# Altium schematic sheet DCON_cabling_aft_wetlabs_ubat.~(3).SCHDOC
size B; Organization: Monterey Bay Aquarium Research Institute; Address1: 7700 Sandholdt Rd; Address2: Moss Landing, CA 95039-9644; CompanyName: MBARI; PageSetup: Record=PageOptions|CenterHorizontal=True|CenterVertical=True|PrintScale=0.70|XCorrection=1.00|YCorrection=1.00|PrintKind=0|BorderSize=5000000|LeftOffset=0|BottomOffset=0|Orientation=2|PaperLength=1000|PaperWidth=1000|Scale=100|PaperSource=7|PrintQuality=-4|MediaType=1|DitherType=10|PaperKind=Letter|PrintScaleMode=1
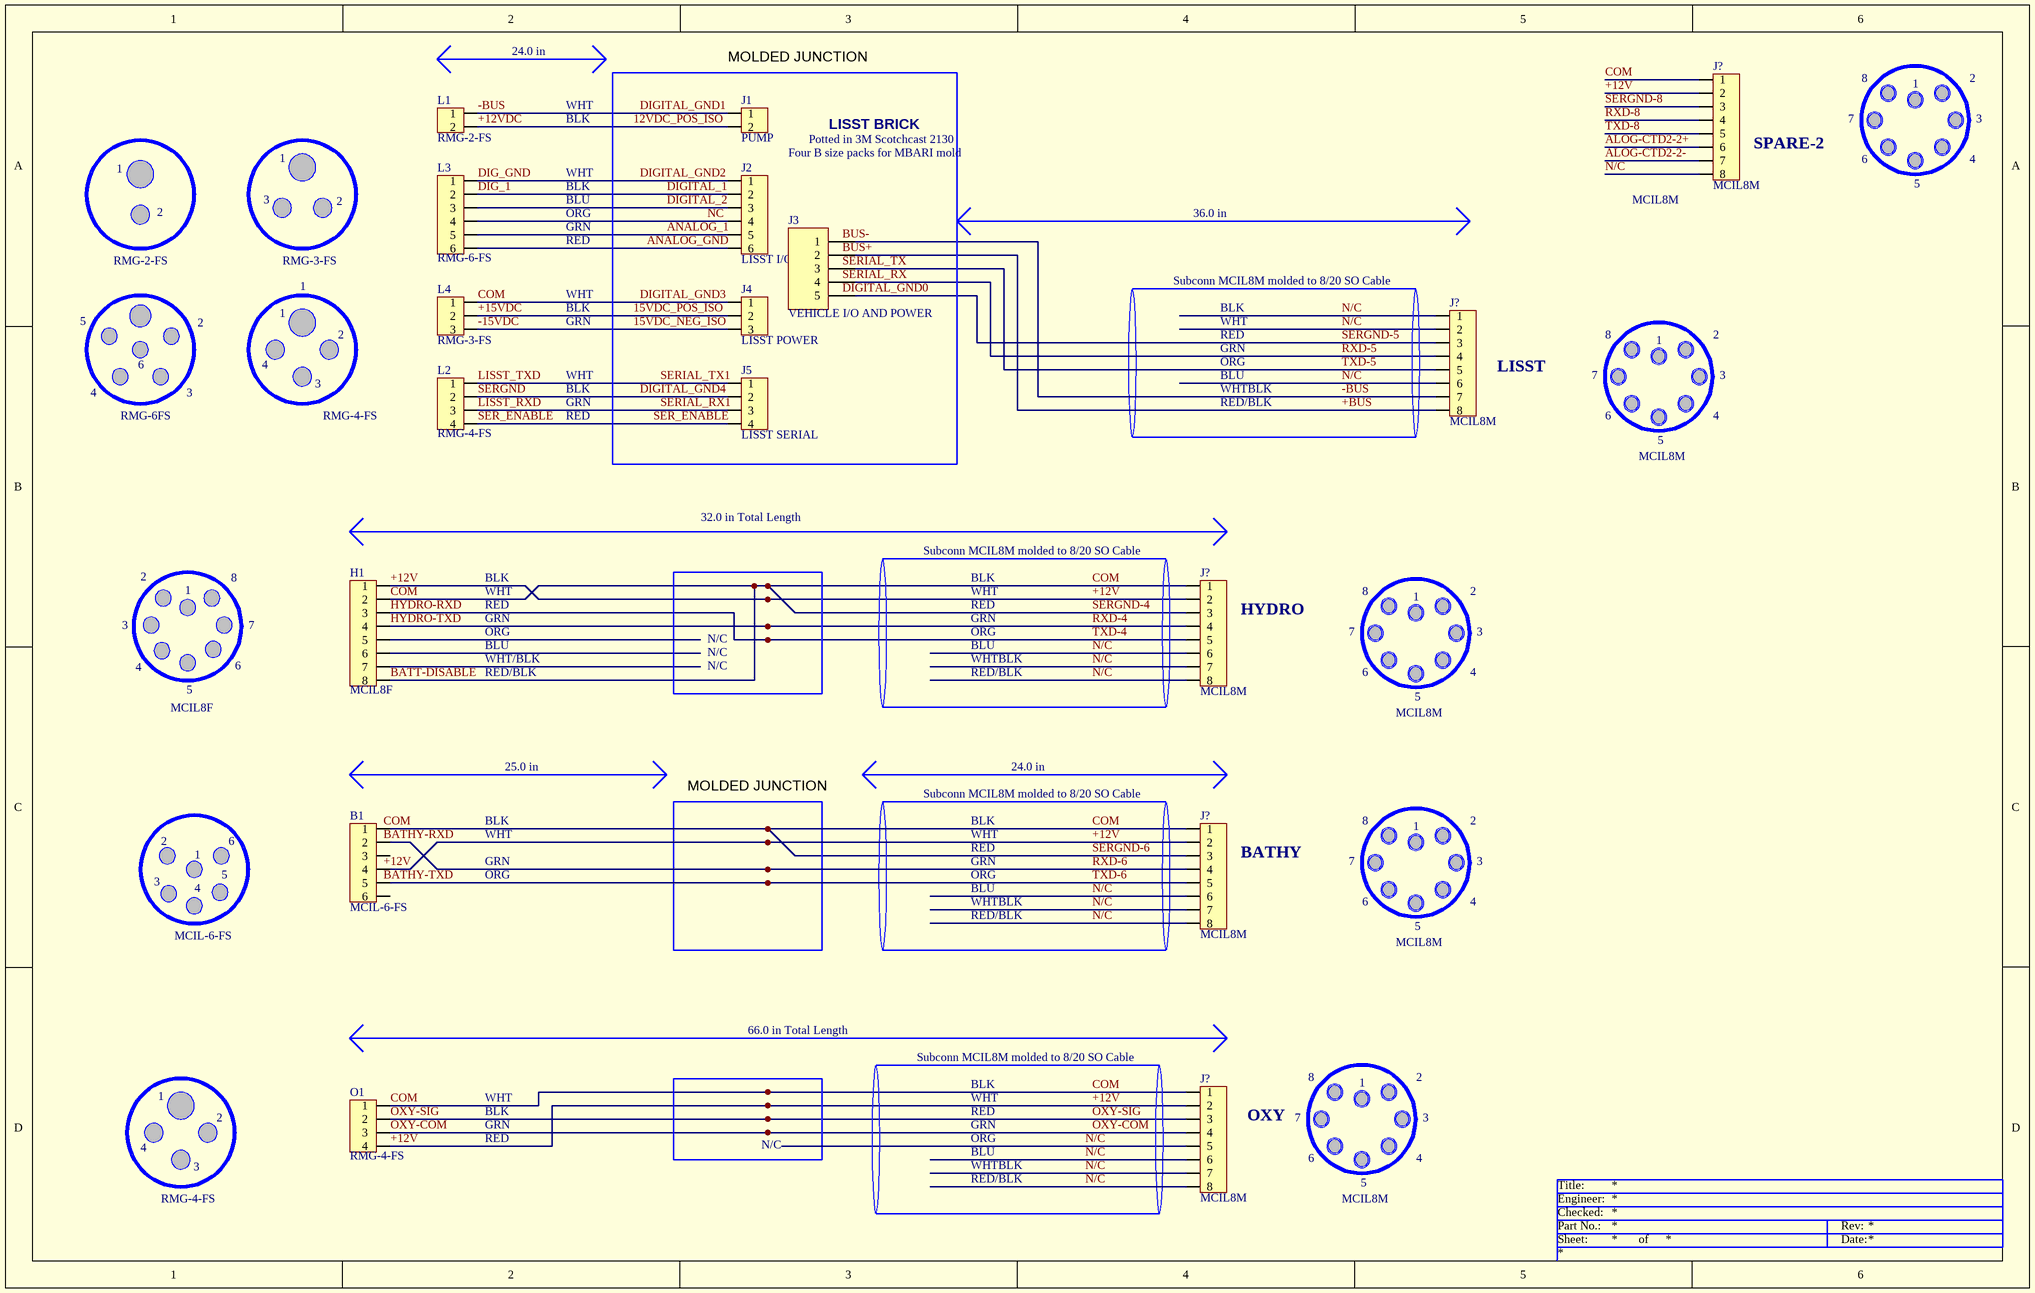
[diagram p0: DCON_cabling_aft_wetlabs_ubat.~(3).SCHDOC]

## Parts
(Parts that share a designator on the sheet are numbered #1, #2 ... from top to bottom, then left to right.)
B1  MCIL-6-FS  [SIP6]
H1  MCIL8F  [SIP6]
J1  PUMP  [SIP6]
J2  LISST I/O  [SIP6]
J3  VEHICLE I/O AND POWER  [HDR1X5]
J4  LISST POWER  [SIP6]
J5  LISST SERIAL  [SIP6]
J?#1  MCIL8M  [SIP8]
J?#2  MCIL8M  [SIP8]
J?#3  MCIL8M  [SIP8]
J?#4  MCIL8M  [SIP8]
J?#5  MCIL8M  [SIP8]
L1  RMG-2-FS  [SIP6]
L2  RMG-4-FS  [SIP6]
L3  RMG-6-FS  [SIP6]
L4  RMG-3-FS  [SIP6]
O1  RMG-4-FS  [SIP6]

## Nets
+12V: B1.4 H1.1 J?#1.2 J?#3.2 J?#4.2 J?#5.2 O1.4
+12VDC: J1.2 L1.2  [also labelled 12VDC_POS_ISO]
+15VDC: J4.2 L4.2  [also labelled 15VDC_POS_ISO]
+BUS: J3.2 J?#2.8
-15VDC: J4.3 L4.3  [also labelled 15VDC_NEG_ISO]
-BUS: J1.1 J3.1 J?#2.7 L1.1  [also labelled DIGITAL_GND1]
ALOG-CTD2-2+: J?#1.6
ALOG-CTD2-2-: J?#1.7
ANALOG_1: J2.5 L3.5
ANALOG_GND: J2.6 L3.6
BATT-DISABLE: B1.1 H1.2 H1.8 J4.1 J?#1.1 J?#3.1 J?#3.3 J?#4.1 J?#4.3 J?#5.1 L4.1 O1.1  [also labelled COM, DIGITAL_GND3, SERGND-4, SERGND-6]
DIG_1: J2.2 L3.2  [also labelled DIGITAL_1]
DIG_GND: J2.1 L3.1  [also labelled DIGITAL_GND2]
DIGITAL_2: J2.3 L3.3
DIGITAL_GND4: J5.2 L2.2  [also labelled SERGND]
HYDRO-RXD: H1.3 J?#3.5  [also labelled TXD-4]
HYDRO-TXD: H1.4 J?#3.4  [also labelled RXD-4]
LISST_RXD: J5.3 L2.3  [also labelled SERIAL_RX1]
LISST_TXD: J5.1 L2.1  [also labelled SERIAL_TX1]
N/C: J?#1.8 J?#2.1 J?#2.2 J?#2.6 J?#3.6 J?#3.7 J?#3.8 J?#4.6 J?#4.7 J?#4.8 J?#5.5 J?#5.6 J?#5.7 J?#5.8
NC: J2.4 L3.4
OXY-COM: J?#5.4 O1.3
OXY-SIG: J?#5.3 O1.2
RXD-5: J3.4 J?#2.4
RXD-6: B1.2 J?#4.4
RXD-8: J?#1.4
SER_ENABLE: J5.4 L2.4
SERGND-5: J3.5 J?#2.3
SERGND-8: J?#1.3
TXD-5: J3.3 J?#2.5
TXD-6: B1.5 J?#4.5
TXD-8: J?#1.5

Not connected (* = marked no-connect by the designer): B1 3 6; H1 5 6 7

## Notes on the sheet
- 24.0 in
- (near J1) MOLDED JUNCTION
- 8
- 1
- 2
- WHT
- BLK
- Four B size packs for MBARI mold
- Potted in 3M Scotchcast 2130
- LISST BRICK
- (near J?#1) SPARE-2
- 7
- 6
- 4
- 3
- BLU
- ORG
- GRN
- 36.0 in
- (near J?#1) MCIL8M
- 5
- RMG-2-FS
- RMG-3-FS
- RED
- (near J?#2) Subconn MCIL8M molded to 8/20 SO Cable
- (near J?#2) LISST
- RMG-6FS
- RMG-4-FS
- RED/BLK
- WHTBLK
- MCIL8M
- 32.0 in Total Length
- (near J?#3) Subconn MCIL8M molded to 8/20 SO Cable
- N/C
- (near J?#3) HYDRO
- WHT/BLK
- MCIL8F
- 25.0 in
- MOLDED JUNCTION
- (near J?#4) Subconn MCIL8M molded to 8/20 SO Cable
- (near J?#4) BATHY
- MCIL-6-FS
- 66.0 in Total Length
- Subconn MCIL8M molded to 8/20 SO Cable
- (near J?#5) OXY
- Labels drawn without touching a wire or pin: +12V, BATHY-RXD, BATHY-TXD, BUS+, BUS-, COM, DIGITAL_GND0, SERIAL_RX, SERIAL_TX

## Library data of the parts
B1 J2 L3 = CON6: Connector
H1 = CON8: Connector
J1 L1 = CON2: Connector
J3 = Header 5: Header, 5-Pin; Manufacturer: Generic Components; Class I: Connector
J4 L4 = CON3: Connector
J5 L2 O1 = CON4: Connector
J?#1-J?#5 = CON8: Connector; ManufPartNo: MCIL8M molded to 24"  8/20 SO Cable; Manufacturer: Subconn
